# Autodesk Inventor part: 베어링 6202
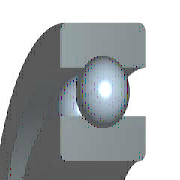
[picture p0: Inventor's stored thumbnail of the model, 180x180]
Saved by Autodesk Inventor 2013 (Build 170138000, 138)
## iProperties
Created: 2015-12
Part Number: 베어링 6202
Material: 강철, 연강
Description: 깊은 그루브 볼 베어링
Document SubType Name: Modeling
Standard: KS B 2023
Designer: mdu
Standards Organization: KS
Language: ko-KR
Size Designation: 6202 - 15 x 35 x 11
Categories: <MemberInstance><Categories><Category DisplayName="샤프트 부품" InternalName="7f7aeb1f-a693-4053-b835-cee3144e0d98" Mnemonic="SHFT"><Category DisplayName="베어링" Inter
Density: 7.86 g/cm^3
Mass: 45.8725 g
Surface Area: 51.5584 cm^2
Volume: 5.83619 cm^3
Company: 한국ATC센터
IsCustomPart: 1
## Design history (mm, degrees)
sketch "스케치" dims "d0" = 5.2 (= -0.26 x WD + 0.26 x BD)
  geometry: L1 (2.9, 12.5)-(8.1, 12.5); L2 (5.5, 12.5)-(5.5, 9.9); L3 (5.5, 12.5)-(5.5, 15.1); L4 (3.568, 10.76)-(0, 10.76); L5 (0, 7.5)-(11, 7.5); L6 (3.568, 14.24)-(0, 14.24); L7 (0, 17.5)-(11, 17.5); L8 (11, 7.5)-(11, 10.76); L9 (7.432, 10.76)-(11, 10.76); L10 (7.432, 14.24)-(11, 14.24); L11 (11, 17.5)-(11, 14.24); L12 (-1.4, 0)-(8.4, 0) reference; L13 (0, -0.3)-(0, 5.3) reference
  constraints: 22 end point, 4 point on line, 2 collinear, 2 perpendicular, 2 symmetric about line, 1 midpoint, 1 parallel, 14 other
  dimensions: "d9" = 15 diameter of L5 L12 (= WD); "d11" = 35 diameter of L7 L12 (= BD); "d12" = 11 distance between parallel lines of L8 L13 (= KB); "d13" = 21.52 diameter of L9 L12 (= 0.326 x BD + 0.674 x WD)
revolve "본체" stored, may be unused: angle "d6" = 90 deg
revolve "볼" stored, may be unused: angle "d7" = 90 deg
pattern_circular "IDS_ARRAYBALL[SIMPL:T]" dims angle "d3" = 360 deg
body "Solid1"
fillet "모깎기1" dims "d1" = 0.6 (= KRS)
other parameters: "WD" = 15 [user parameter; used in 5 equation terms], "BD" = 35 [user parameter; used in 5 equation terms], "KB" = 11 [user parameter; used in 1 equation term], "KRS" = 0.6 [user parameter; used in 1 equation term], "d4" = 0, "d5" = 0, "d8" = 0, "d14" = 0, "d15" = 0, "BBA" = 0 [user parameter], "BC0" = 3750000 [user parameter], "BC" = 7800000 [user parameter], "BR" = 17.5 (= 0.5 x BD) [user parameter], "WR" = 7.5 (= 0.5 x WD) [user parameter]
